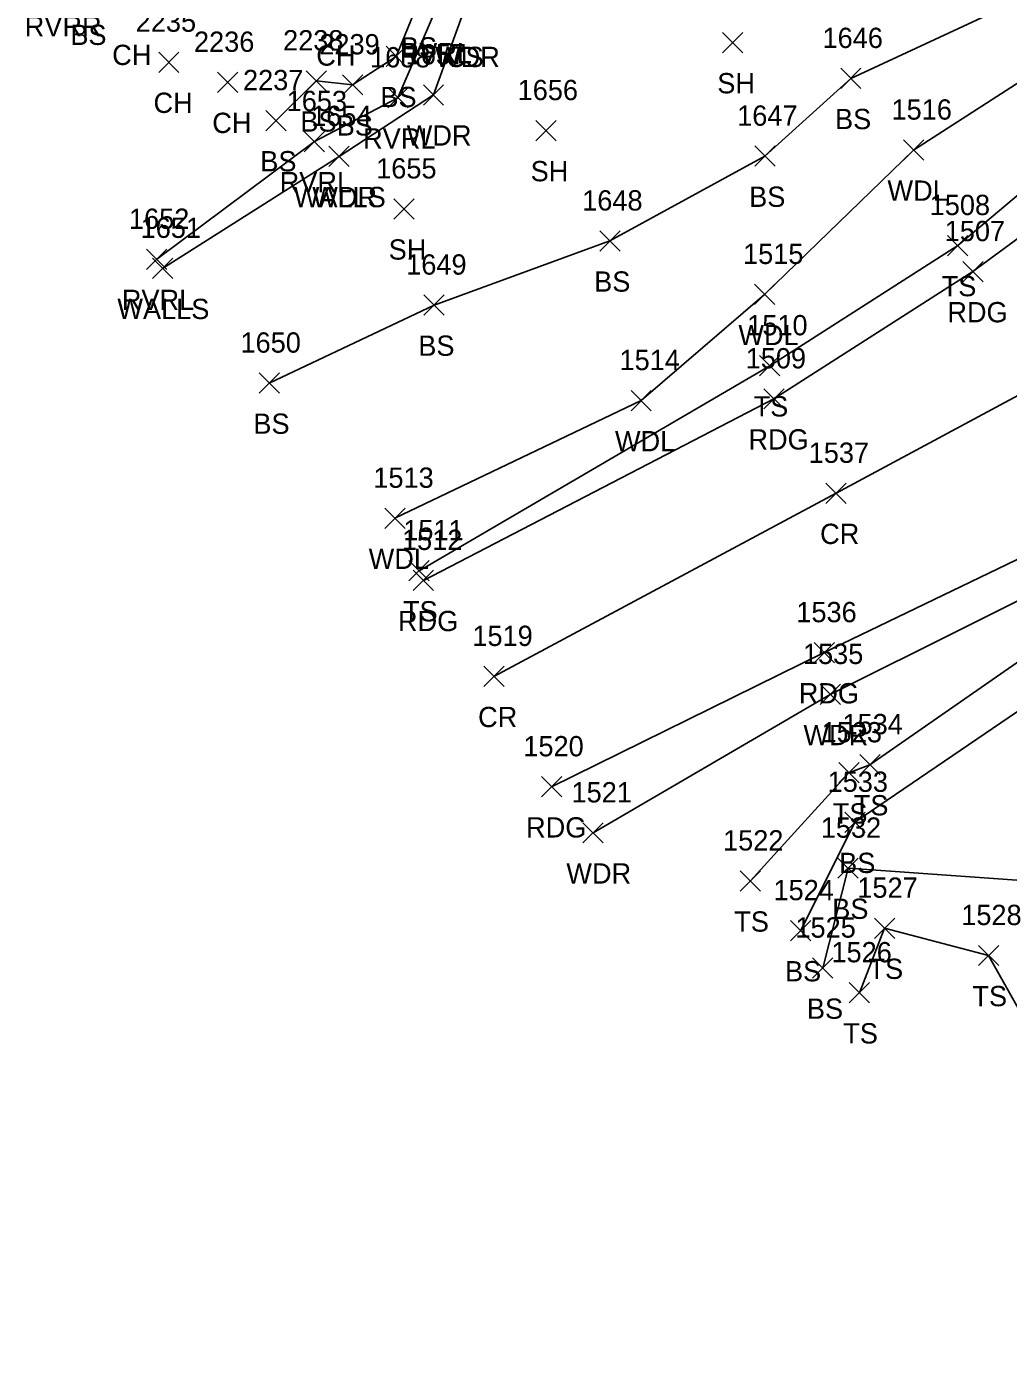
# Model space of a CAD drawing. Extents: x 1501299 to 1502485, y 381423 to 383765.
# Drawn here: x 1501492.4 to 1501589, y 383093.5 to 383226.1 of the extents above; entities that cross this region are included whole.
import ezdxf

# ---------------------------------------------------------------- set-up
doc = ezdxf.new("R2010")
doc.units = 0
for name, color, linetype in [('L_A', 7, 'Continuous'), ('L_I', 7, 'Continuous'), ('L_TIC', 7, 'Continuous'), ('LAWA', 7, 'Continuous'), ('LAWE', 7, 'Continuous'), ('LELB', 7, 'Continuous'), ('LWS', 7, 'Continuous'), ('P_A', 7, 'Continuous'), ('P_I', 7, 'Continuous'), ('P_TIC', 7, 'Continuous'), ('PEU', 7, 'Continuous'), ('PRC', 7, 'Continuous')]:
    doc.layers.add(name, color=color, linetype=linetype)

msp = doc.modelspace()

# ---------------------------------------------------------------- linework, layer by layer
at = {"layer": 'L_TIC'}
for points in [[(1501560.9, 383223.53), (1501562.9, 383225.53)], [(1501562.9, 383223.53), (1501560.9, 383225.53)], [(1501527.75, 383222.17), (1501529.75, 383224.17)], [(1501529.75, 383222.17), (1501527.75, 383224.17)], [(1501505.35, 383221.6), (1501507.35, 383223.6)], [(1501507.35, 383221.6), (1501505.35, 383223.6)], [(1501511.15, 383219.62), (1501513.15, 383221.62)], [(1501513.15, 383219.62), (1501511.15, 383221.62)], [(1501519.87, 383219.76), (1501521.87, 383221.76)], [(1501521.87, 383219.76), (1501519.87, 383221.76)], [(1501523.45, 383219.37), (1501525.45, 383221.37)], [(1501525.45, 383219.37), (1501523.45, 383221.37)], [(1501572.55, 383220), (1501574.55, 383222)], [(1501574.55, 383220), (1501572.55, 383222)], [(1501527.92, 383218.09), (1501529.92, 383220.09)], [(1501529.92, 383218.09), (1501527.92, 383220.09)], [(1501531.43, 383218.38), (1501533.43, 383220.38)], [(1501533.43, 383218.38), (1501531.43, 383220.38)], [(1501515.92, 383215.84), (1501517.92, 383217.84)], [(1501517.92, 383215.84), (1501515.92, 383217.84)], [(1501542.51, 383214.86), (1501544.51, 383216.86)], [(1501544.51, 383214.86), (1501542.51, 383216.86)], [(1501519.7, 383213.78), (1501521.7, 383215.78)], [(1501521.7, 383213.78), (1501519.7, 383215.78)], [(1501578.74, 383212.94), (1501580.74, 383214.94)], [(1501580.74, 383212.94), (1501578.74, 383214.94)], [(1501522.12, 383212.31), (1501524.12, 383214.31)], [(1501524.12, 383212.31), (1501522.12, 383214.31)], [(1501522.12, 383212.31), (1501524.12, 383214.31)], [(1501524.12, 383212.31), (1501522.12, 383214.31)], [(1501564.09, 383212.34), (1501566.09, 383214.34)], [(1501566.09, 383212.34), (1501564.09, 383214.34)], [(1501528.52, 383207.14), (1501530.52, 383209.14)], [(1501530.52, 383207.14), (1501528.52, 383209.14)], [(1501548.82, 383203.98), (1501550.82, 383205.98)], [(1501550.82, 383203.98), (1501548.82, 383205.98)], [(1501583.09, 383203.53), (1501585.09, 383205.53)], [(1501585.09, 383203.53), (1501583.09, 383205.53)], [(1501504.16, 383202.17), (1501506.16, 383204.17)], [(1501506.16, 383202.17), (1501504.16, 383204.17)], [(1501504.74, 383201.28), (1501506.74, 383203.28)], [(1501506.74, 383201.28), (1501504.74, 383203.28)], [(1501564.06, 383198.71), (1501566.06, 383200.71)], [(1501566.06, 383198.71), (1501564.06, 383200.71)], [(1501531.49, 383197.66), (1501533.49, 383199.66)], [(1501533.49, 383197.66), (1501531.49, 383199.66)], [(1501564.56, 383191.68), (1501566.56, 383193.68)], [(1501566.56, 383191.68), (1501564.56, 383193.68)], [(1501515.24, 383189.97), (1501517.24, 383191.97)], [(1501517.24, 383189.97), (1501515.24, 383191.97)], [(1501551.89, 383188.25), (1501553.89, 383190.25)], [(1501553.89, 383188.25), (1501551.89, 383190.25)], [(1501527.63, 383176.65), (1501529.63, 383178.65)], [(1501529.63, 383176.65), (1501527.63, 383178.65)], [(1501530.01, 383171.48), (1501532.01, 383173.48)], [(1501532.01, 383171.48), (1501530.01, 383173.48)], [(1501570.52, 383159.28), (1501572.52, 383161.28)], [(1501572.52, 383159.28), (1501570.52, 383161.28)], [(1501574.43, 383152.36), (1501576.43, 383154.36)], [(1501576.43, 383152.36), (1501574.43, 383154.36)], [(1501572.36, 383151.56), (1501574.36, 383153.56)], [(1501574.36, 383151.56), (1501572.36, 383153.56)], [(1501572.96, 383146.68), (1501574.96, 383148.68)], [(1501574.96, 383146.68), (1501572.96, 383148.68)], [(1501547.16, 383145.64), (1501549.16, 383147.64)], [(1501549.16, 383145.64), (1501547.16, 383147.64)], [(1501572.28, 383142.16), (1501574.28, 383144.16)], [(1501574.28, 383142.16), (1501572.28, 383144.16)], [(1501562.65, 383140.9), (1501564.65, 383142.9)], [(1501564.65, 383140.9), (1501562.65, 383142.9)], [(1501567.62, 383136), (1501569.62, 383138)], [(1501569.62, 383136), (1501567.62, 383138)], [(1501575.88, 383136.24), (1501577.88, 383138.24)], [(1501577.88, 383136.24), (1501575.88, 383138.24)], [(1501586.12, 383133.55), (1501588.12, 383135.55)], [(1501588.12, 383133.55), (1501586.12, 383135.55)], [(1501569.78, 383132.31), (1501571.78, 383134.31)], [(1501571.78, 383132.31), (1501569.78, 383134.31)], [(1501573.39, 383129.88), (1501575.39, 383131.88)], [(1501575.39, 383129.88), (1501573.39, 383131.88)]]:
    msp.add_lwpolyline(points, dxfattribs=at)
at = {"layer": 'LAWA'}
for points in [[(1501523.12, 383213.31), (1501532.43, 383219.38), (1501535.22, 383227.12), (1501552.76, 383237.53), (1501565.99, 383247.18), (1501582.96, 383255.3), (1501593.87, 383261.82), (1501604.57, 383266.91)], [(1501528.63, 383177.65), (1501552.89, 383189.25), (1501565.06, 383199.71), (1501579.74, 383213.94), (1501595.13, 383223.84), (1501608.97, 383230.54), (1501610.44, 383240.69), (1501611.93, 383256.47), (1501604.57, 383266.91)], [(1501548.16, 383146.64), (1501571.52, 383160.28), (1501598.46, 383173.71), (1501618.34, 383183.18), (1501640.68, 383191.3), (1501653.61, 383191.95), (1501667.48, 383171.42), (1501677.43, 383157.35), (1501677.3, 383139.43), (1501665.74, 383124.94), (1501648.24, 383107.59), (1501635.22, 383093.49)]]:
    msp.add_lwpolyline(points, dxfattribs=at)
at = {"layer": 'LAWE'}
msp.add_lwpolyline([(1501505.16, 383203.17), (1501520.7, 383214.78), (1501528.92, 383219.09), (1501532.52, 383227.49), (1501551.85, 383239.1), (1501563.53, 383248.35), (1501581.91, 383257.47), (1501592.13, 383263.02), (1501602.49, 383268.62), (1501606.54, 383268.13), (1501609.9, 383267.24)], dxfattribs=at)
at = {"layer": 'LELB'}
for points in [[(1501619.16, 383281.8), (1501618.61, 383281.1), (1501625.91, 383269.99), (1501629.16, 383260.71), (1501626.95, 383253.59), (1501623.52, 383242.3), (1501612.25, 383228.2), (1501584.09, 383204.53), (1501565.56, 383192.68), (1501531.01, 383172.48)], [(1501605.35, 383233.31), (1501590.6, 383228.95), (1501573.55, 383221), (1501565.09, 383213.34), (1501549.82, 383204.98), (1501532.49, 383198.66), (1501516.24, 383190.97)], [(1501516.92, 383216.84), (1501520.87, 383220.76), (1501524.45, 383220.37), (1501528.75, 383223.17), (1501530.77, 383228.06)], [(1501563.65, 383141.9), (1501573.36, 383152.56), (1501575.43, 383153.36), (1501618.34, 383183.18)], [(1501568.62, 383137), (1501573.96, 383147.68), (1501597.16, 383163.48)], [(1501570.78, 383133.31), (1501573.28, 383143.16), (1501595.46, 383141.58), (1501596.32, 383132.48), (1501607.32, 383126.04), (1501611.75, 383126.46), (1501628.45, 383133.28), (1501633.11, 383139.35), (1501631.71, 383151.93), (1501644.31, 383161.99)], [(1501574.39, 383130.88), (1501576.88, 383137.24), (1501587.12, 383134.55), (1501591.98, 383125.92), (1501605.91, 383116.3), (1501617.18, 383118.06), (1501635.07, 383129.08), (1501644.68, 383143.1), (1501638.02, 383150.19), (1501648.46, 383156.85), (1501654.99, 383162.15), (1501659.59, 383155.1), (1501663.43, 383147.57), (1501672.93, 383137.11), (1501665.74, 383124.94)]]:
    msp.add_lwpolyline(points, dxfattribs=at)
at = {"layer": 'LWS'}
msp.add_lwpolyline([(1501505.74, 383202.28), (1501523.12, 383213.31)], dxfattribs=at)
at = {"layer": 'P_TIC'}
for points in [[(1501584.58, 383200.96), (1501586.58, 383202.96)], [(1501586.58, 383200.96), (1501584.58, 383202.96)], [(1501564.97, 383188.42), (1501566.97, 383190.42)], [(1501566.97, 383188.42), (1501564.97, 383190.42)], [(1501571.09, 383179.11), (1501573.09, 383181.11)], [(1501573.09, 383179.11), (1501571.09, 383181.11)], [(1501530.44, 383170.52), (1501532.44, 383172.52)], [(1501532.44, 383170.52), (1501530.44, 383172.52)], [(1501569.93, 383163.4), (1501571.93, 383165.4)], [(1501571.93, 383163.4), (1501569.93, 383165.4)], [(1501537.39, 383161.06), (1501539.39, 383163.06)], [(1501539.39, 383161.06), (1501537.39, 383163.06)], [(1501543.06, 383150.18), (1501545.06, 383152.18)], [(1501545.06, 383150.18), (1501543.06, 383152.18)]]:
    msp.add_lwpolyline(points, dxfattribs=at)
at = {"layer": 'PEU'}
for points in [[(1501626.93, 383271.2), (1501631.33, 383262.38), (1501631.11, 383252.37), (1501628.78, 383235.24), (1501616.1, 383224.37), (1501585.58, 383201.96), (1501565.97, 383189.42), (1501531.44, 383171.52)], [(1501544.06, 383151.18), (1501570.93, 383164.4), (1501598.87, 383177.9), (1501615.32, 383186.88), (1501641.2, 383196.91), (1501662.06, 383199.17), (1501675.7, 383198.29)]]:
    msp.add_lwpolyline(points, dxfattribs=at)
at = {"layer": 'PRC'}
msp.add_lwpolyline([(1501538.39, 383162.06), (1501572.09, 383180.11), (1501595.76, 383192.82), (1501620.62, 383207.91), (1501642.7, 383221.82), (1501654.42, 383229.17)], dxfattribs=at)

# ---------------------------------------------------------------- texts
at = {"layer": 'L_A'}
for s, p in [('RVRR', (1501492.15, 383225.14)), ('BS', (1501496.64, 383224.3)), ('CH', (1501500.77, 383222.32)), ('CH', (1501520.88, 383222.26)), ('RVRL', (1501529.09, 383222.49)), ('BS', (1501529.21, 383223.06)), ('WDR', (1501532.58, 383222.12)), ('CS', (1501533.66, 383222.12)), ('SH', (1501560.39, 383219.53)), ('BS', (1501527.19, 383218.17)), ('CH', (1501504.84, 383217.6)), ('CH', (1501510.63, 383215.62)), ('BS', (1501519.31, 383215.76)), ('BS', (1501522.89, 383215.37)), ('BS', (1501571.99, 383216)), ('RVRL', (1501525.49, 383214.09)), ('WDR', (1501529.79, 383214.38)), ('BS', (1501515.36, 383211.84)), ('SH', (1501542, 383210.86)), ('RVRL', (1501517.27, 383209.78)), ('WDL', (1501577.16, 383208.94)), ('WALLS', (1501518.66, 383208.31)), ('WDR', (1501520.48, 383208.31)), ('BS', (1501563.53, 383208.34)), ('SH', (1501528.01, 383203.14)), ('BS', (1501548.26, 383199.98)), ('TS', (1501582.5, 383199.53)), ('RVRL', (1501501.72, 383198.17)), ('WALLS', (1501501.28, 383197.28)), ('WDL', (1501562.47, 383194.71)), ('BS', (1501530.93, 383193.66)), ('TS', (1501563.97, 383187.68)), ('BS', (1501514.68, 383185.97)), ('WDL', (1501550.31, 383184.25)), ('WDL', (1501526.04, 383172.65)), ('TS', (1501529.42, 383167.48)), ('WDR', (1501568.88, 383155.28)), ('TS', (1501573.84, 383148.36)), ('TS', (1501571.77, 383147.56)), ('BS', (1501572.4, 383142.68)), ('WDR', (1501545.52, 383141.64)), ('BS', (1501571.72, 383138.16)), ('TS', (1501562.06, 383136.9)), ('BS', (1501567.06, 383132)), ('TS', (1501575.29, 383132.24)), ('TS', (1501585.53, 383129.55)), ('BS', (1501569.22, 383128.31)), ('TS', (1501572.8, 383125.88))]:
    msp.add_text(s, height=2, dxfattribs=at).set_placement(p)
at = {"layer": 'L_I'}
for s, p in [('2235', (1501503.09, 383225.6)), ('2236', (1501508.83, 383223.62)), ('2238', (1501517.61, 383223.76)), ('2239', (1501521.18, 383223.37)), ('1646', (1501570.76, 383224)), ('1658', (1501526.18, 383222.09)), ('1657', (1501529.69, 383222.38)), ('2237', (1501513.66, 383219.84)), ('1656', (1501540.72, 383218.86)), ('1653', (1501517.96, 383217.78)), ('1516', (1501577.56, 383216.94)), ('1654', (1501520.38, 383216.31)), ('1654', (1501520.38, 383216.31)), ('1647', (1501562.35, 383216.34)), ('1655', (1501526.78, 383211.14)), ('1648', (1501547.08, 383207.98)), ('1508', (1501581.32, 383207.53)), ('1652', (1501502.42, 383206.17)), ('1651', (1501503.57, 383205.28)), ('1515', (1501562.93, 383202.71)), ('1649', (1501529.74, 383201.66)), ('1510', (1501563.34, 383195.68)), ('1650', (1501513.41, 383193.97)), ('1514', (1501550.76, 383192.25)), ('1513', (1501526.5, 383180.65)), ('1511', (1501529.45, 383175.48)), ('1535', (1501568.83, 383163.28)), ('1534', (1501572.73, 383156.36)), ('1523', (1501570.67, 383155.56)), ('1533', (1501571.26, 383150.68)), ('1521', (1501546.03, 383149.64)), ('1532', (1501570.59, 383146.16)), ('1522', (1501560.96, 383144.9)), ('1524', (1501565.93, 383140)), ('1527', (1501574.19, 383140.24)), ('1528', (1501584.43, 383137.55)), ('1525', (1501568.09, 383136.31)), ('1526', (1501571.64, 383133.88))]:
    msp.add_text(s, height=2, dxfattribs=at).set_placement(p)
at = {"layer": 'P_A'}
for s, p in [('RDG', (1501583.06, 383196.96)), ('RDG', (1501563.46, 383184.42)), ('CR', (1501570.52, 383175.11)), ('RDG', (1501528.93, 383166.52)), ('RDG', (1501568.42, 383159.4)), ('CR', (1501536.82, 383157.06)), ('RDG', (1501541.55, 383146.18))]:
    msp.add_text(s, height=2, dxfattribs=at).set_placement(p)
at = {"layer": 'P_I'}
for s, p in [('1507', (1501582.8, 383204.96)), ('1509', (1501563.19, 383192.42)), ('1537', (1501569.4, 383183.11)), ('1512', (1501529.32, 383174.52)), ('1536', (1501568.18, 383167.4)), ('1519', (1501536.26, 383165.06)), ('1520', (1501541.28, 383154.18))]:
    msp.add_text(s, height=2, dxfattribs=at).set_placement(p)

doc.saveas('drawing.dxf')
